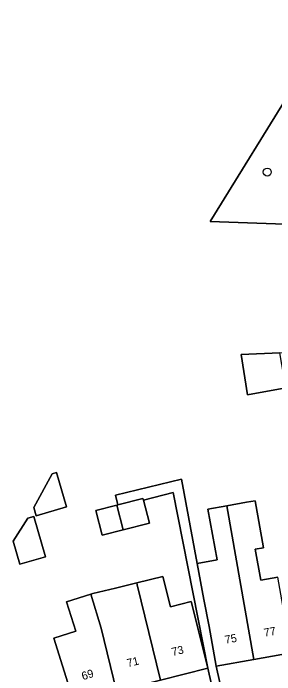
# Model space of a CAD drawing. Extents: x 160157 to 160921, y 381516 to 382045.
# Drawn here: x 160418.3 to 160450.7, y 381723.6 to 381805.6 of the extents above; entities that cross this region are included whole.
import ezdxf

# ---------------------------------------------------------------- set-up
doc = ezdxf.new("R2010")
doc.units = 0
for name, color, linetype in [('IMGEO_Boom', 7, 'Continuous'), ('IMGEO_Erf', 7, 'Continuous'), ('IMGEO_Groenvoorziening', 7, 'Continuous'), ('IMGEO_Pand', 7, 'Continuous'), ('IMGEO_Pand_nummerreeks', 7, 'Continuous'), ('IMGEO_Voetpad_open', 7, 'Continuous')]:
    doc.layers.add(name, color=color, linetype=linetype)

msp = doc.modelspace()

# ---------------------------------------------------------------- linework, layer by layer
at = {"layer": 'IMGEO_Boom'}
msp.add_circle((160449.734, 381785.912), 0.489, dxfattribs=at)
at = {"layer": 'IMGEO_Erf'}
for points in [[(160458.476, 381723.221), (160493.473, 381729.503), (160494.638, 381750), (160495.695, 381777.781), (160473.521, 381778.628), (160459.011, 381779.182), (160455.366, 381779.322), (160442.688, 381779.806), (160453.283, 381796.984), (160458.209, 381794.524), (160460.339, 381798.072), (160463.455, 381800.599), (160473.68, 381809.649)], [(160478.111, 381761.891), (160483.435, 381761.689), (160483.56, 381764.319), (160487.098, 381764.173), (160492.094, 381763.983), (160491.871, 381758.315), (160491.648, 381752.629), (160491.545, 381750), (160491.441, 381747.357), (160491.186, 381740.846), (160490.949, 381734.797), (160489.727, 381733.038), (160477.25, 381730.792), (160472.561, 381729.947), (160467.851, 381729.099), (160462.186, 381728.079), (160457.509, 381727.237), (160452.68, 381726.368), (160448.085, 381725.541), (160443.422, 381724.701), (160444.327, 381720.659)], [(160443.305, 381720.427), (160442.382, 381724.436), (160438.098, 381746.2), (160434.412, 381745.253), (160435.139, 381742.423), (160431.894, 381741.59), (160429.304, 381740.925), (160428.516, 381743.995), (160431.106, 381744.66), (160431.229, 381744.692), (160430.936, 381745.898), (160439.118, 381747.885), (160441.064, 381737.44), (160443.525, 381737.883), (160442.398, 381744.144), (160444.726, 381744.563), (160447.187, 381745.006), (160448.226, 381745.193), (160449.275, 381739.367), (160448.236, 381739.18), (160448.923, 381735.366), (160451.034, 381735.746)]]:
    msp.add_lwpolyline(points, dxfattribs=at)
for points in [[(160451.296, 381763.518), (160455.802, 381763.698), (160456.483, 381759.963), (160452.039, 381759.176), (160447.279, 381758.333), (160446.516, 381763.327)], [(160423.658, 381748.695), (160424.882, 381744.423), (160421.122, 381743.345), (160420.827, 381744.373), (160423.088, 381748.532)], [(160420.116, 381743.047), (160420.841, 381743.255), (160422.281, 381738.23), (160419.109, 381737.321), (160418.289, 381740.184)], [(160442.382, 381724.436), (160436.504, 381722.975), (160431.065, 381721.617), (160425.888, 381719.981), (160424.38, 381724.749), (160423.295, 381728.182), (160426.048, 381729.052), (160424.9, 381732.683), (160427.914, 381733.636), (160428.133, 381733.705), (160430.954, 381734.36), (160433.583, 381735.013), (160436.82, 381735.818), (160437.753, 381732.067), (160440.325, 381732.707), (160441.175, 381729.289)]]:
    msp.add_lwpolyline(points, close=True, dxfattribs=at)
at = {"layer": 'IMGEO_Groenvoorziening'}
msp.add_lwpolyline([(160458.948, 381780.395), (160458.371, 381791.432), (160458.209, 381794.524), (160453.283, 381796.984), (160442.688, 381779.806), (160455.366, 381779.322), (160459.011, 381779.182)], close=True, dxfattribs=at)
at = {"layer": 'IMGEO_Pand'}
for points in [[(160451.296, 381763.518), (160446.516, 381763.327), (160447.279, 381758.333), (160452.039, 381759.176)], [(160420.827, 381744.373), (160421.122, 381743.345), (160424.882, 381744.423), (160423.658, 381748.695), (160423.088, 381748.532)], [(160434.412, 381745.253), (160434.351, 381745.492), (160431.229, 381744.692), (160431.106, 381744.66), (160431.894, 381741.59), (160435.139, 381742.423)], [(160431.106, 381744.66), (160428.516, 381743.995), (160429.304, 381740.925), (160431.894, 381741.59)], [(160447.187, 381745.006), (160444.726, 381744.563), (160448.085, 381725.541), (160452.68, 381726.368), (160451.034, 381735.746), (160448.923, 381735.366), (160448.236, 381739.18), (160449.275, 381739.367), (160448.226, 381745.193)], [(160444.726, 381744.563), (160442.398, 381744.144), (160443.525, 381737.883), (160441.064, 381737.44), (160441.896, 381732.975), (160442.536, 381729.622), (160443.422, 381724.701), (160448.085, 381725.541)], [(160419.109, 381737.321), (160422.281, 381738.23), (160420.841, 381743.255), (160420.116, 381743.047), (160418.289, 381740.184)], [(160433.583, 381735.013), (160433.633, 381734.795), (160436.504, 381722.975), (160442.382, 381724.436), (160441.175, 381729.289), (160440.325, 381732.707), (160437.753, 381732.067), (160436.82, 381735.818)], [(160433.583, 381735.013), (160430.954, 381734.36), (160428.133, 381733.705), (160427.914, 381733.636), (160429.178, 381729.423), (160431.065, 381721.617), (160436.504, 381722.975), (160433.633, 381734.795)], [(160427.914, 381733.636), (160424.9, 381732.683), (160426.048, 381729.052), (160423.295, 381728.182), (160424.38, 381724.749), (160425.888, 381719.981), (160431.065, 381721.617), (160429.178, 381729.423)]]:
    msp.add_lwpolyline(points, close=True, dxfattribs=at)
at = {"layer": 'IMGEO_Voetpad_open'}
msp.add_lwpolyline([(160442.536, 381729.622), (160441.896, 381732.975), (160441.064, 381737.44), (160439.118, 381747.885), (160430.936, 381745.898), (160431.229, 381744.692), (160434.351, 381745.492), (160434.412, 381745.253), (160438.098, 381746.2), (160442.382, 381724.436), (160443.305, 381720.427), (160444.327, 381720.659), (160443.422, 381724.701)], close=True, dxfattribs=at)

# ---------------------------------------------------------------- texts
at = {"layer": 'IMGEO_Pand_nummerreeks'}
for s, rotation, p in [('77', 10.20438, (160449.411, 381728.339)), ('75', 10.20649, (160444.578, 381727.469)), ('73', 13.96309, (160438.033, 381725.952)), ('71', 14.01091, (160432.483, 381724.569)), ('69', 17.53967, (160426.929, 381722.953))]:
    msp.add_text(s, height=1, rotation=rotation, dxfattribs=at).set_placement(p)

doc.saveas('drawing.dxf')
